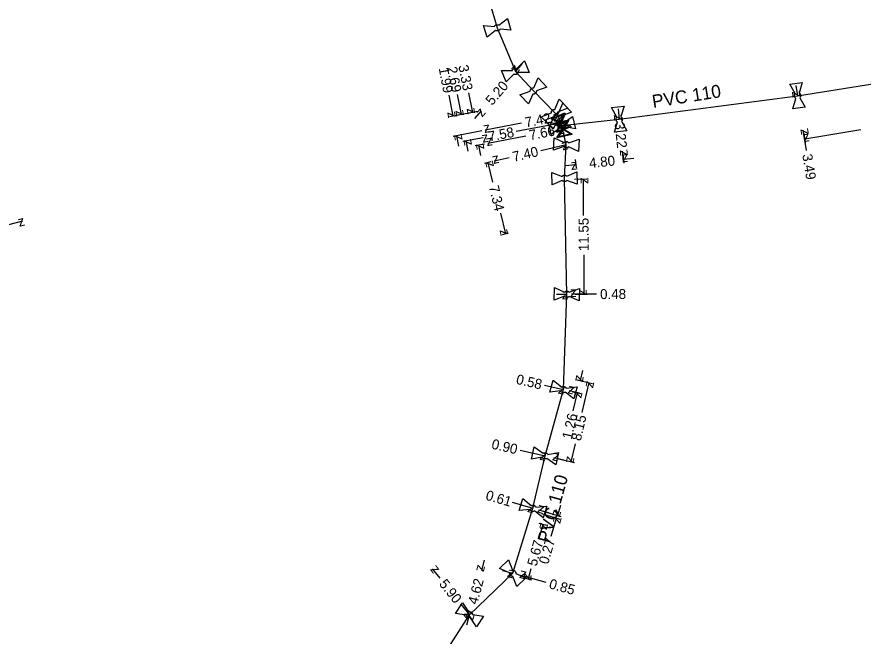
# Model space of a CAD drawing. Extents: x -638315 to -636370, y -1116147 to -1115110.
# Drawn here: x -637075.6 to -636990.8, y -1115952.2 to -1115890.1 of the extents above; entities that cross this region are included whole.
import ezdxf

# ---------------------------------------------------------------- set-up
doc = ezdxf.new("R2010")
doc.units = 0
for name, color, linetype in [('Default', 7, 'Continuous'), ('VP Kótování', 7, 'Continuous'), ('VP Lomový bod', 7, 'Continuous'), ('VP Řad', 7, 'Continuous'), ('VP Řad - popis', 7, 'Continuous'), ('VP Šoupě', 7, 'Continuous')]:
    doc.layers.add(name, color=color, linetype=linetype)

msp = doc.modelspace()

# ---------------------------------------------------------------- linework, layer by layer
at = {"layer": 'Default'}
for points in [[(-637027.785, -1115891.09), (-637027.763, -1115891.042), (-637027.725, -1115891.003), (-637027.667, -1115890.943), (-637027.588, -1115890.92), (-637027.51, -1115890.897), (-637027.425, -1115890.917), (-637027.373, -1115890.928), (-637027.329, -1115890.957)], [(-637027.214, -1115891.35), (-637027.236, -1115891.397), (-637027.273, -1115891.436), (-637027.334, -1115891.497), (-637027.412, -1115891.52), (-637027.491, -1115891.543), (-637027.573, -1115891.523), (-637027.626, -1115891.511), (-637027.67, -1115891.482)], [(-637025.977, -1115895.493), (-637025.961, -1115895.443), (-637025.928, -1115895.4), (-637025.876, -1115895.333), (-637025.801, -1115895.302), (-637025.725, -1115895.27), (-637025.639, -1115895.281), (-637025.586, -1115895.287), (-637025.539, -1115895.311)], [(-637025.382, -1115895.688), (-637025.398, -1115895.737), (-637025.431, -1115895.78), (-637025.485, -1115895.847), (-637025.56, -1115895.879), (-637025.636, -1115895.91), (-637025.719, -1115895.9), (-637025.774, -1115895.894), (-637025.821, -1115895.87)], [(-637024.192, -1115897.56), (-637024.194, -1115897.507), (-637024.177, -1115897.455), (-637024.151, -1115897.375), (-637024.091, -1115897.32), (-637024.031, -1115897.265), (-637023.946, -1115897.245), (-637023.895, -1115897.232), (-637023.842, -1115897.239)], [(-637023.566, -1115897.54), (-637023.565, -1115897.592), (-637023.581, -1115897.643), (-637023.608, -1115897.725), (-637023.668, -1115897.78), (-637023.729, -1115897.836), (-637023.811, -1115897.855), (-637023.864, -1115897.867), (-637023.916, -1115897.86)], [(-636997.581, -1115898.291), (-636997.625, -1115898.262), (-636997.658, -1115898.219), (-636997.709, -1115898.152), (-636997.719, -1115898.07), (-636997.73, -1115897.989), (-636997.698, -1115897.909), (-636997.678, -1115897.859), (-636997.643, -1115897.82)], [(-636997.237, -1115897.767), (-636997.194, -1115897.796), (-636997.161, -1115897.838), (-636997.11, -1115897.908), (-636997.1, -1115897.989), (-636997.089, -1115898.07), (-636997.121, -1115898.148), (-636997.141, -1115898.199), (-636997.177, -1115898.238)], [(-637022.072, -1115899.73), (-637022.076, -1115899.677), (-637022.061, -1115899.625), (-637022.038, -1115899.544), (-637021.979, -1115899.486), (-637021.921, -1115899.429), (-637021.837, -1115899.407), (-637021.786, -1115899.392), (-637021.733, -1115899.397)], [(-637021.447, -1115899.689), (-637021.444, -1115899.741), (-637021.458, -1115899.793), (-637021.483, -1115899.875), (-637021.541, -1115899.933), (-637021.6, -1115899.99), (-637021.681, -1115900.012), (-637021.734, -1115900.026), (-637021.787, -1115900.021)], [(-637021.718, -1115900.093), (-637021.721, -1115900.04), (-637021.705, -1115899.988), (-637021.68, -1115899.907), (-637021.621, -1115899.851), (-637021.561, -1115899.795), (-637021.477, -1115899.774), (-637021.426, -1115899.761), (-637021.373, -1115899.766)], [(-637021.092, -1115900.063), (-637021.09, -1115900.115), (-637021.105, -1115900.167), (-637021.132, -1115900.249), (-637021.191, -1115900.305), (-637021.251, -1115900.361), (-637021.332, -1115900.381), (-637021.385, -1115900.395), (-637021.438, -1115900.389)], [(-637015.457, -1115900.638), (-637015.5, -1115900.608), (-637015.532, -1115900.564), (-637015.582, -1115900.495), (-637015.59, -1115900.414), (-637015.599, -1115900.333), (-637015.565, -1115900.253), (-637015.545, -1115900.204), (-637015.508, -1115900.166)], [(-637015.102, -1115900.121), (-637015.059, -1115900.151), (-637015.028, -1115900.194), (-637014.978, -1115900.265), (-637014.969, -1115900.346), (-637014.96, -1115900.427), (-637014.994, -1115900.505), (-637015.015, -1115900.555), (-637015.051, -1115900.593)], [(-637021.297, -1115900.864), (-637021.272, -1115900.817), (-637021.232, -1115900.781), (-637021.17, -1115900.724), (-637021.09, -1115900.706), (-637021.01, -1115900.687), (-637020.927, -1115900.712), (-637020.876, -1115900.727), (-637020.834, -1115900.758)], [(-637020.743, -1115901.157), (-637020.767, -1115901.203), (-637020.806, -1115901.239), (-637020.871, -1115901.297), (-637020.951, -1115901.315), (-637021.03, -1115901.333), (-637021.111, -1115901.309), (-637021.163, -1115901.293), (-637021.206, -1115901.262)], [(-637020.807, -1115902.713), (-637020.77, -1115902.676), (-637020.723, -1115902.651), (-637020.645, -1115902.614), (-637020.563, -1115902.618), (-637020.481, -1115902.623), (-637020.411, -1115902.668), (-637020.364, -1115902.697), (-637020.332, -1115902.739)], [(-637020.354, -1115903.146), (-637020.39, -1115903.185), (-637020.439, -1115903.209), (-637020.515, -1115903.247), (-637020.596, -1115903.242), (-637020.678, -1115903.238), (-637020.751, -1115903.191), (-637020.796, -1115903.163), (-637020.828, -1115903.121)], [(-637021.001, -1115906.111), (-637020.968, -1115906.07), (-637020.921, -1115906.042), (-637020.849, -1115905.999), (-637020.767, -1115905.997), (-637020.685, -1115905.996), (-637020.609, -1115906.037), (-637020.562, -1115906.062), (-637020.527, -1115906.101)], [(-637020.518, -1115906.51), (-637020.552, -1115906.55), (-637020.597, -1115906.578), (-637020.672, -1115906.621), (-637020.754, -1115906.622), (-637020.836, -1115906.624), (-637020.91, -1115906.584), (-637020.958, -1115906.558), (-637020.993, -1115906.519)], [(-637020.29, -1115918.143), (-637020.326, -1115918.182), (-637020.374, -1115918.207), (-637020.449, -1115918.246), (-637020.531, -1115918.243), (-637020.613, -1115918.24), (-637020.687, -1115918.194), (-637020.732, -1115918.167), (-637020.765, -1115918.126)], [(-637020.75, -1115917.717), (-637020.715, -1115917.679), (-637020.668, -1115917.654), (-637020.59, -1115917.615), (-637020.509, -1115917.618), (-637020.427, -1115917.621), (-637020.355, -1115917.665), (-637020.309, -1115917.694), (-637020.276, -1115917.735)], [(-637020.686, -1115927.75), (-637020.73, -1115927.78), (-637020.783, -1115927.793), (-637020.865, -1115927.813), (-637020.944, -1115927.791), (-637021.022, -1115927.769), (-637021.084, -1115927.708), (-637021.122, -1115927.671), (-637021.144, -1115927.623)], [(-637021.034, -1115927.229), (-637020.99, -1115927.2), (-637020.939, -1115927.187), (-637020.855, -1115927.167), (-637020.776, -1115927.189), (-637020.697, -1115927.211), (-637020.638, -1115927.271), (-637020.599, -1115927.31), (-637020.577, -1115927.358)], [(-637022.525, -1115934.381), (-637022.567, -1115934.413), (-637022.62, -1115934.428), (-637022.7, -1115934.452), (-637022.78, -1115934.434), (-637022.86, -1115934.416), (-637022.924, -1115934.357), (-637022.963, -1115934.322), (-637022.988, -1115934.275)], [(-637022.896, -1115933.876), (-637022.854, -1115933.846), (-637022.803, -1115933.83), (-637022.72, -1115933.807), (-637022.64, -1115933.825), (-637022.56, -1115933.843), (-637022.498, -1115933.9), (-637022.458, -1115933.937), (-637022.433, -1115933.984)], [(-637023.755, -1115939.655), (-637023.799, -1115939.683), (-637023.853, -1115939.694), (-637023.935, -1115939.712), (-637024.013, -1115939.688), (-637024.091, -1115939.664), (-637024.151, -1115939.6), (-637024.188, -1115939.562), (-637024.208, -1115939.513)], [(-637024.086, -1115939.123), (-637024.042, -1115939.096), (-637023.99, -1115939.084), (-637023.905, -1115939.067), (-637023.827, -1115939.091), (-637023.749, -1115939.116), (-637023.692, -1115939.177), (-637023.654, -1115939.217), (-637023.633, -1115939.265)], [(-637025.932, -1115946.212), (-637025.985, -1115946.215), (-637026.037, -1115946.199), (-637026.118, -1115946.175), (-637026.175, -1115946.116), (-637026.232, -1115946.057), (-637026.253, -1115945.973), (-637026.267, -1115945.922), (-637026.262, -1115945.87)], [(-637025.967, -1115945.586), (-637025.915, -1115945.583), (-637025.864, -1115945.598), (-637025.781, -1115945.624), (-637025.725, -1115945.683), (-637025.668, -1115945.742), (-637025.647, -1115945.823), (-637025.633, -1115945.876), (-637025.639, -1115945.929)], [(-637030.191, -1115950.369), (-637030.241, -1115950.385), (-637030.296, -1115950.382), (-637030.38, -1115950.377), (-637030.449, -1115950.333), (-637030.517, -1115950.289), (-637030.558, -1115950.212), (-637030.583, -1115950.165), (-637030.59, -1115950.113)], [(-637030.369, -1115949.769), (-637030.319, -1115949.754), (-637030.266, -1115949.757), (-637030.18, -1115949.763), (-637030.111, -1115949.807), (-637030.042, -1115949.851), (-637030.003, -1115949.926), (-637029.977, -1115949.974), (-637029.97, -1115950.026)]]:
    msp.add_open_spline(points, degree=3, dxfattribs=at)
at = {"layer": 'VP Kótování'}
for points in [[(-637024.995, -1115894.794), (-637025.68, -1115895.59)], [(-636997.581, -1115896.994), (-636997.41, -1115898.03)], [(-637032.337, -1115897.988), (-637031.932, -1115900.083)], [(-637031.504, -1115897.915), (-637031.115, -1115899.925)], [(-637030.369, -1115897.743), (-637029.99, -1115899.708)], [(-637029.414, -1115899.596), (-637032.276, -1115900.149)], [(-637029.414, -1115899.596), (-637031.459, -1115899.992)], [(-637029.414, -1115899.596), (-637030.334, -1115899.774)], [(-637029.755, -1115900.326), (-637029.07, -1115899.53)], [(-637015.388, -1115899.336), (-637015.28, -1115900.38)], [(-637025.061, -1115900.785), (-637028.692, -1115901.487)], [(-637025.587, -1115901.593), (-637021.12, -1115900.73)], [(-637029.036, -1115901.553), (-637031.898, -1115902.106)], [(-637031.355, -1115903.071), (-637031.554, -1115902.04)], [(-637028.904, -1115902.234), (-637030.949, -1115902.63)], [(-637024.641, -1115902.069), (-637028.438, -1115902.802)], [(-636996.505, -1115903.516), (-636996.842, -1115901.474)], [(-636996.785, -1115901.819), (-636996.634, -1115902.734)], [(-636991.049, -1115901.459), (-636996.691, -1115902.389)], [(-637030.406, -1115903.594), (-637030.605, -1115902.563)], [(-637028.782, -1115902.868), (-637029.702, -1115903.046)], [(-637029.159, -1115904.011), (-637029.358, -1115902.98)], [(-637023.116, -1115903.512), (-637020.58, -1115902.93)], [(-637014.84, -1115904.63), (-637014.948, -1115903.586)], [(-637014.912, -1115903.934), (-637014.825, -1115904.778)], [(-637028.131, -1115904.669), (-637028.761, -1115904.823)], [(-637027.944, -1115906.693), (-637028.421, -1115904.74)], [(-637026.297, -1115904.243), (-637027.791, -1115904.586)], [(-637019.684, -1115904.428), (-637019.597, -1115905.272)], [(-637013.816, -1115904.321), (-637014.861, -1115904.429)], [(-637020.677, -1115905.032), (-637019.633, -1115904.923)], [(-637019.74, -1115906.379), (-637018.512, -1115906.374)], [(-637018.847, -1115910.052), (-637018.862, -1115906.375)], [(-637027.183, -1115909.81), (-637026.68, -1115911.874)], [(-637079.528, -1115911.726), (-637075.04, -1115910.57)], [(-637026.39, -1115911.803), (-637027.02, -1115911.957)], [(-637018.832, -1115913.962), (-637018.816, -1115917.923)], [(-637021.57, -1115917.934), (-637020.52, -1115917.93)], [(-637017.543, -1115917.917), (-637020.044, -1115917.928)], [(-637019.694, -1115917.927), (-637018.466, -1115917.922)], [(-637018.943, -1115925.558), (-637019.179, -1115926.581)], [(-637019.669, -1115926.468), (-637018.838, -1115926.66)], [(-637019.669, -1115926.468), (-637017.944, -1115926.865)], [(-637018.976, -1115929.792), (-637018.285, -1115926.787)], [(-637022.775, -1115927.051), (-637020.86, -1115927.49)], [(-637019.27, -1115927.855), (-637020.293, -1115927.62)], [(-637019.952, -1115927.698), (-637019.121, -1115927.89)], [(-637019.875, -1115929.607), (-637019.462, -1115927.811)], [(-637025.185, -1115933.561), (-637022.71, -1115934.13)], [(-637019.696, -1115932.921), (-637020.111, -1115934.728)], [(-637020.813, -1115934.566), (-637021.836, -1115934.331)], [(-637021.495, -1115934.409), (-637019.77, -1115934.806)], [(-637026.018, -1115938.778), (-637023.92, -1115939.39)], [(-637022.326, -1115939.855), (-637023.334, -1115939.561)], [(-637021.176, -1115939.1), (-637021.472, -1115940.108)], [(-637023.074, -1115939.919), (-637021.212, -1115940.465)], [(-637022.998, -1115939.66), (-637021.136, -1115940.206)], [(-637022.081, -1115942.185), (-637021.548, -1115940.367)], [(-637023.332, -1115940.883), (-637022.571, -1115941.091)], [(-637023.285, -1115942.374), (-637022.908, -1115940.999)], [(-637028.819, -1115944.595), (-637029.09, -1115945.61)], [(-637033.213, -1115946.405), (-637033.97, -1115945.46)], [(-637024.134, -1115945.468), (-637024.408, -1115946.469)], [(-637026.963, -1115945.622), (-637025.95, -1115945.9)], [(-637022.585, -1115946.823), (-637025.133, -1115946.124)], [(-637024.832, -1115946.353), (-637024.071, -1115946.561)], [(-637031.174, -1115948.954), (-637030.28, -1115950.07)], [(-637030.551, -1115951.085), (-637030.28, -1115950.07)]]:
    msp.add_lwpolyline(points, dxfattribs=at)
at = {"layer": 'VP Lomový bod'}
for points in [[(-637027.329, -1115890.957), (-637026.476, -1115890.269)], [(-637026.476, -1115890.269), (-637026.125, -1115891.468), (-637027.214, -1115891.35)], [(-637027.67, -1115891.482), (-637028.524, -1115892.171), (-637028.875, -1115890.971), (-637027.785, -1115891.09)], [(-637025.539, -1115895.311), (-637024.767, -1115894.533)], [(-637024.767, -1115894.533), (-637024.286, -1115895.687), (-637025.382, -1115895.688)], [(-637025.821, -1115895.87), (-637026.594, -1115896.648), (-637027.075, -1115895.494), (-637025.977, -1115895.493)], [(-637023.842, -1115897.239), (-637023.382, -1115896.244)], [(-637023.382, -1115896.244), (-637022.536, -1115897.165), (-637023.566, -1115897.54)], [(-636998.192, -1115896.872), (-636996.953, -1115896.709), (-636997.237, -1115897.767)], [(-636997.643, -1115897.82), (-636998.192, -1115896.872)], [(-637023.916, -1115897.86), (-637024.378, -1115898.856), (-637025.223, -1115897.935), (-637024.192, -1115897.56)], [(-637021.733, -1115899.397), (-637021.306, -1115898.388)], [(-637021.306, -1115898.388), (-637020.43, -1115899.28), (-637021.447, -1115899.689)], [(-637021.373, -1115899.766), (-637020.927, -1115898.765)], [(-637020.927, -1115898.765), (-637020.068, -1115899.673), (-637021.092, -1115900.063)], [(-636997.177, -1115898.238), (-636996.627, -1115899.188), (-636997.866, -1115899.351), (-636997.581, -1115898.291)], [(-637016.037, -1115899.206), (-637014.795, -1115899.069), (-637015.102, -1115900.121)], [(-637015.508, -1115900.166), (-637016.037, -1115899.206)], [(-637021.787, -1115900.021), (-637022.215, -1115901.031), (-637023.09, -1115900.139), (-637022.072, -1115899.73)], [(-637021.438, -1115900.389), (-637021.885, -1115901.391), (-637022.744, -1115900.483), (-637021.718, -1115900.093)], [(-637020.834, -1115900.758), (-637019.942, -1115900.122)], [(-637019.942, -1115900.122), (-637019.662, -1115901.34), (-637020.743, -1115901.157)], [(-637021.206, -1115901.262), (-637022.099, -1115901.899), (-637022.378, -1115900.68), (-637021.297, -1115900.864)], [(-637015.051, -1115900.593), (-637014.522, -1115901.554), (-637015.765, -1115901.691), (-637015.457, -1115900.638)], [(-637021.861, -1115903.488), (-637021.795, -1115902.24), (-637020.807, -1115902.713)], [(-637020.332, -1115902.739), (-637019.298, -1115902.373), (-637019.365, -1115903.621), (-637020.354, -1115903.146)], [(-637020.828, -1115903.121), (-637021.861, -1115903.488)], [(-637020.993, -1115906.519), (-637021.997, -1115906.961), (-637022.023, -1115905.711), (-637021.001, -1115906.111)], [(-637020.527, -1115906.101), (-637019.524, -1115905.659)], [(-637019.524, -1115905.659), (-637019.498, -1115906.909), (-637020.518, -1115906.51)], [(-637021.791, -1115918.511), (-637021.747, -1115917.261), (-637020.75, -1115917.717)], [(-637020.276, -1115917.735), (-637019.248, -1115917.35), (-637019.293, -1115918.599), (-637020.29, -1115918.143)], [(-637020.765, -1115918.126), (-637021.791, -1115918.511)], [(-637022.232, -1115927.757), (-637021.896, -1115926.553), (-637021.034, -1115927.229)], [(-637021.144, -1115927.623), (-637022.232, -1115927.757)], [(-637020.577, -1115927.358), (-637019.488, -1115927.224), (-637019.823, -1115928.428), (-637020.686, -1115927.75)], [(-637024.068, -1115934.458), (-637023.788, -1115933.24), (-637022.896, -1115933.876)], [(-637022.988, -1115934.275), (-637024.068, -1115934.458)], [(-637022.433, -1115933.984), (-637021.352, -1115933.801), (-637021.632, -1115935.019), (-637022.525, -1115934.381)], [(-637025.3, -1115939.614), (-637024.927, -1115938.421), (-637024.086, -1115939.123)], [(-637024.208, -1115939.513), (-637025.3, -1115939.614)], [(-637023.633, -1115939.265), (-637022.541, -1115939.165), (-637022.913, -1115940.358), (-637023.755, -1115939.655)], [(-637027.267, -1115945.433), (-637026.367, -1115944.566), (-637025.967, -1115945.586)], [(-637026.262, -1115945.87), (-637027.267, -1115945.433)], [(-637025.639, -1115945.929), (-637024.632, -1115946.366), (-637025.533, -1115947.233), (-637025.932, -1115946.212)], [(-637031.669, -1115949.921), (-637030.994, -1115948.869), (-637030.369, -1115949.769)], [(-637030.59, -1115950.113), (-637031.669, -1115949.921)], [(-637029.97, -1115950.026), (-637028.89, -1115950.219), (-637029.565, -1115951.271), (-637030.191, -1115950.369)]]:
    msp.add_lwpolyline(points, dxfattribs=at)
at = {"layer": 'VP Řad'}
for points in [[(-637074.96, -1115821.37), (-637064.392, -1115832.177), (-637062.269, -1115834.347), (-637054.22, -1115842.43), (-637048.649, -1115846.013), (-637043.32, -1115848.63), (-637040.36, -1115852.39), (-637038.75, -1115856.5), (-637037.2, -1115862.58), (-637034.55, -1115868.19), (-637032.96, -1115872.76), (-637032.085, -1115875.699), (-637031.05, -1115879.175), (-637029.56, -1115884.18), (-637027.5, -1115891.22), (-637025.68, -1115895.59), (-637023.88, -1115897.55), (-637021.76, -1115899.71), (-637021.41, -1115900.08), (-637021.02, -1115901.01)], [(-637021.02, -1115901.01), (-637015.28, -1115900.38), (-636997.41, -1115898.03), (-636972.48, -1115894.07), (-636962.1, -1115892.77), (-636955.701, -1115890.614)], [(-637090.11, -1116022.496), (-637088.015, -1116021.282), (-637068.04, -1116008.27), (-637063.353, -1116003.45), (-637050.99, -1115988.7), (-637046.76, -1115976.44), (-637033.727, -1115955.44), (-637030.28, -1115950.07), (-637025.95, -1115945.9), (-637023.92, -1115939.39), (-637022.71, -1115934.13), (-637020.86, -1115927.49), (-637020.52, -1115917.93), (-637020.76, -1115906.31), (-637020.58, -1115902.93), (-637021.02, -1115901.01)]]:
    msp.add_lwpolyline(points, dxfattribs=at)
at = {"layer": 'VP Šoupě'}
for points in [[(-637020.139, -1115901.131), (-637021.522, -1115901.711), (-637021.547, -1115901.651), (-637021.495, -1115901.533), (-637021.178, -1115900.755), (-637022.077, -1115900.389), (-637022.102, -1115900.328), (-637020.719, -1115899.748), (-637020.693, -1115899.809), (-637021.063, -1115900.707), (-637020.285, -1115901.024), (-637020.164, -1115901.07), (-637020.139, -1115901.131)], [(-637021.925, -1115900.356), (-637021.144, -1115900.674), (-637020.827, -1115899.895), (-637021.925, -1115900.356)], [(-637020.022, -1115901.913), (-637021.484, -1115902.248), (-637021.499, -1115902.184), (-637021.427, -1115902.077), (-637020.981, -1115901.365), (-637021.804, -1115900.85), (-637021.819, -1115900.786), (-637020.357, -1115900.451), (-637020.342, -1115900.515), (-637020.86, -1115901.337), (-637020.148, -1115901.783), (-637020.037, -1115901.849), (-637020.022, -1115901.913)], [(-637021.65, -1115900.843), (-637020.935, -1115901.29), (-637020.489, -1115900.577), (-637021.65, -1115900.843)], [(-637020.32, -1115901.106), (-637021.096, -1115900.789), (-637021.412, -1115901.564), (-637020.32, -1115901.106)], [(-637020.196, -1115901.857), (-637020.907, -1115901.412), (-637021.351, -1115902.121), (-637020.196, -1115901.857)]]:
    msp.add_lwpolyline(points, dxfattribs=at)

# ---------------------------------------------------------------- texts
at = {"layer": 'VP Kótování'}
for s, rotation, p in [('1.99', 280.93221, (-637033.37, -1115895.276)), ('2.69', 280.94189, (-637032.537, -1115895.203)), ('3.33', 280.93227, (-637031.402, -1115895.032)), ('z', 229.29108, (-637025.733, -1115894.885)), ('5.20', 49.2911, (-637028.009, -1115899.063)), ('z', 279.36519, (-636997.985, -1115897.618)), ('z', 280.93223, (-637032.518, -1115899.687)), ('z', 280.94191, (-637031.701, -1115899.529)), ('z', 280.93228, (-637030.576, -1115899.312)), ('z', 49.2911, (-637029.017, -1115900.235)), ('7.42', 10.9357, (-637024.622, -1115901.21)), ('z', 10.9357, (-637021.806, -1115900.666)), ('z', 10.9392, (-637021.516, -1115901.316)), ('z', 275.91226, (-637015.829, -1115899.934)), ('z', 190.93574, (-637028.296, -1115900.901)), ('7.58', 10.9392, (-637028.299, -1115902.627)), ('7.66', 10.93129, (-637024.203, -1115902.493)), ('z', 10.93129, (-637021.316, -1115901.936)), ('3.22', 275.91224, (-637015.745, -1115900.741)), ('z', 99.36515, (-636996.267, -1115901.886)), ('z', 100.93219, (-637030.968, -1115902.436)), ('z', 10.9392, (-637028.956, -1115902.754)), ('z', 190.93133, (-637028.042, -1115902.216)), ('z', 189.35684, (-636996.279, -1115901.814)), ('z', 100.94193, (-637030.019, -1115902.959)), ('z', 100.9323, (-637028.772, -1115903.376)), ('z', 12.93366, (-637020.955, -1115903.529)), ('7.40', 12.93366, (-637025.844, -1115904.652)), ('z', 95.91222, (-637014.399, -1115904.032)), ('z', 185.91021, (-637014.415, -1115903.881)), ('3.49', 279.36517, (-636996.942, -1115903.943)), ('z', 103.71453, (-637027.816, -1115905.107)), ('z', 192.93364, (-637027.416, -1115903.987)), ('z', 5.91023, (-637020.079, -1115905.472)), ('4.80', 5.91023, (-637018.238, -1115905.282)), ('z', 90.22825, (-637018.36, -1115906.873)), ('7.34', 283.71455, (-637028.347, -1115907.152)), ('z', 14.4371, (-637075.4, -1115911.179)), ('11.55', 90.22825, (-637018.333, -1115913.61)), ('z', 283.71457, (-637027.284, -1115911.506)), ('z', 180.24074, (-637019.546, -1115917.426)), ('z', 270.22823, (-637019.318, -1115917.425)), ('0.48', 0.24076, (-637017.191, -1115918.416)), ('z', 0.24076, (-637021.018, -1115918.432)), ('0.58', 347.0866, (-637025.673, -1115926.9)), ('z', 257.04281, (-637019.554, -1115925.982)), ('z', 77.05016, (-637017.91, -1115927.386)), ('z', 347.08656, (-637021.459, -1115927.866)), ('z', 167.08658, (-637019.694, -1115927.244)), ('z', 77.04283, (-637019.087, -1115928.411)), ('1.26', 77.04283, (-637020.036, -1115932.537)), ('8.15', 77.05016, (-637019.13, -1115932.692)), ('0.90', 347.0485, (-637028.137, -1115933.395)), ('z', 347.04846, (-637023.309, -1115934.505)), ('z', 167.04848, (-637021.237, -1115933.956)), ('z', 257.0502, (-637020.486, -1115934.128)), ('0.61', 343.73228, (-637028.734, -1115938.506)), ('z', 343.7323, (-637024.54, -1115939.73)), ('z', 163.73226, (-637022.714, -1115939.221)), ('z', 253.64637, (-637021.811, -1115939.487)), ('z', 73.64639, (-637021.209, -1115940.987)), ('z', 74.66517, (-637022.558, -1115941.613)), ('5.67', 74.66517, (-637023.559, -1115945.263)), ('0.27', 73.64639, (-637022.406, -1115945.069)), ('z', 128.67498, (-637033.267, -1115945.538)), ('z', 255.0606, (-637029.444, -1115944.998)), ('z', 344.66776, (-637026.564, -1115946.25)), ('z', 164.66778, (-637024.519, -1115945.774)), ('z', 254.66515, (-637024.758, -1115945.854)), ('5.90', 308.67494, (-637033.385, -1115946.991)), ('4.62', 75.06057, (-637029.504, -1115949.1)), ('0.85', 344.66775, (-637022.38, -1115947.397)), ('z', 308.67496, (-637030.983, -1115949.992)), ('z', 75.06057, (-637029.926, -1115950.682))]:
    msp.add_text(s, height=1, rotation=rotation, dxfattribs=at).set_placement(p)
at = {"layer": 'VP Řad - popis'}
for rotation, p in [(9.02575, (-637011.872, -1115899.255)), (74.4314, (-637022.252, -1115942.948))]:
    msp.add_text('PVC 110', height=1.3, rotation=rotation, dxfattribs=at).set_placement(p)

doc.saveas('drawing.dxf')
